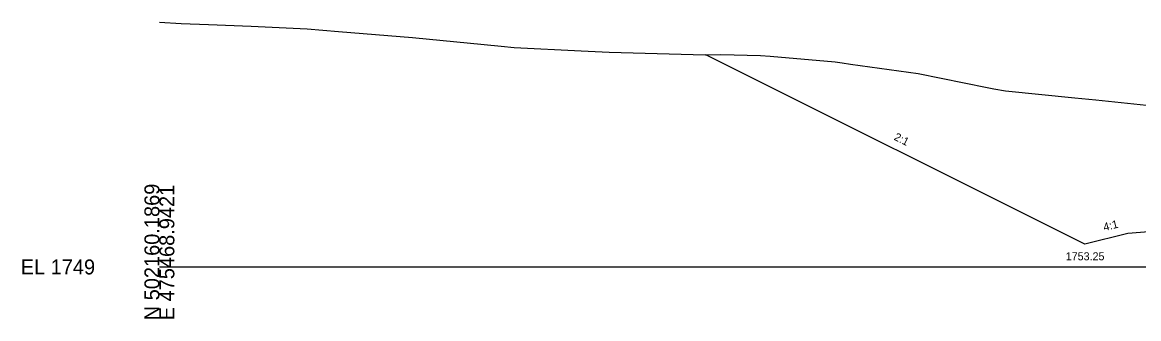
# Model space of a CAD drawing. Extents: x -26 to 1803, y -10 to 9558.
# Drawn here: x -25.7 to 183.5, y 7490.3 to 7545.9 of the extents above; entities that cross this region are included whole.
import ezdxf

# ---------------------------------------------------------------- set-up
doc = ezdxf.new("R2010")
doc.units = 0
for name, color, linetype in [('Exist Cross Section Cell', 7, 'Continuous'), ('Exist XS Ground Line', 7, 'Continuous'), ('Prop XS Ditch Slope Text', 7, 'Continuous'), ('Prop XS Ditch Standard Text', 7, 'Continuous'), ('Prop XS Dump Level', 7, 'Continuous'), ('Prop XS Earthwork Shape', 7, 'Continuous'), ('Prop XS Finish Grade Earthwork', 7, 'Continuous'), ('Prop XS Hydro Typical Ditch Data', 7, 'Continuous'), ('Prop XS Side Slope Text', 7, 'Continuous')]:
    doc.layers.add(name, color=color, linetype=linetype)

msp = doc.modelspace()

# ---------------------------------------------------------------- linework, layer by layer
at = {"layer": 'Exist Cross Section Cell'}
msp.add_line((0, 7500), (200, 7500), dxfattribs=at)
at = {"layer": 'Exist XS Ground Line'}
msp.add_lwpolyline([(0, 7545.85), (4.09, 7545.66), (9.18, 7545.43), (17.17, 7545.11), (27.7, 7544.62), (33.58, 7544.14), (47.43, 7542.98), (60.87, 7541.67), (64.07, 7541.37), (66.5, 7541.12), (79.04, 7540.49), (84.27, 7540.24), (102.28, 7539.77), (105.22, 7539.82), (112.64, 7539.65), (114.48, 7539.48), (126.65, 7538.44), (127.95, 7538.28), (129.53, 7537.99), (142.19, 7536.26), (155.12, 7533.62), (156.42, 7533.39), (158.56, 7533), (171.58, 7531.71), (175.54, 7531.31), (187.37, 7530.05)], dxfattribs=at)
at = {"layer": 'Prop XS Earthwork Shape'}
msp.add_lwpolyline([(185.45, 7506.57), (181.49, 7506.25), (173.48, 7504.25), (102.41, 7539.78), (105.22, 7539.82), (112.64, 7539.65), (114.48, 7539.48), (126.65, 7538.44), (127.95, 7538.28), (129.53, 7537.99), (142.19, 7536.26), (155.12, 7533.62), (156.42, 7533.39), (158.56, 7533), (171.58, 7531.71), (175.54, 7531.31), (187.37, 7530.05)], dxfattribs=at)
at = {"layer": 'Prop XS Finish Grade Earthwork'}
for p, q in [((173.48, 7504.25), (102.41, 7539.78)), ((181.49, 7506.25), (173.48, 7504.25)), ((185.45, 7506.57), (181.49, 7506.25))]:
    msp.add_line(p, q, dxfattribs=at)
at = {"layer": 'Prop XS Hydro Typical Ditch Data'}
for p, q in [((173.48, 7504.25), (102.41, 7539.78)), ((181.49, 7506.25), (173.48, 7504.25))]:
    msp.add_line(p, q, dxfattribs=at)

# ---------------------------------------------------------------- texts
at = {"layer": 'Exist Cross Section Cell'}
for s, p in [('N 502160.1869', (0, 7490)), ('E 475468.9421', (2.8, 7490))]:
    msp.add_text(s, height=2.8, rotation=90, dxfattribs=at).set_placement(p)
msp.add_text('EL 1749', height=2.8, dxfattribs=at).set_placement((-26, 7498.6))
at = {"layer": 'Prop XS Ditch Slope Text'}
msp.add_text('4:1', height=1.5, rotation=14.0305, dxfattribs=at).set_placement((177.12, 7506.71))
at = {"layer": 'Prop XS Ditch Standard Text'}
msp.add_text('1753.25', height=1.5, dxfattribs=at).set_placement((169.88, 7501.25))
at = {"layer": 'Prop XS Dump Level'}
msp.add_text('Case1', height=0.04, dxfattribs=at).set_placement((181.49, 7506.21))
at = {"layer": 'Prop XS Side Slope Text'}
msp.add_text('2:1', height=1.5, rotation=333.4447, dxfattribs=at).set_placement((137.55, 7523.89))

doc.saveas('drawing.dxf')
